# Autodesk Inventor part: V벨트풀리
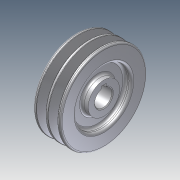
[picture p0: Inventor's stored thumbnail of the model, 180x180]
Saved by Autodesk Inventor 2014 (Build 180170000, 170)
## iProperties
Company: 한국ATC센터
Created: 2015-02
Part Number: V벨트풀리
Document SubType Name: Modeling
Designer: KYOUNG IL JANG
Density: 1 g/cm^3
Material: 일반
Appearance: 기본값
Author: KYOUNG IL JANG
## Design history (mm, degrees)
sketch "스케치1"
  geometry: L1 (0, 0)-(35, 0); L2 (35, 0)-(35, 55); L3 (35, 55)-(31.062, 55); L4 (31.062, 55)-(27.001, 42.5); L5 (27.001, 42.5)-(22.999, 42.5); L6 (22.999, 42.5)-(18.938, 55); L7 (18.938, 55)-(16.062, 55); L8 (16.062, 55)-(12.001, 42.5); L9 (12.001, 42.5)-(7.999, 42.5); L10 (7.999, 42.5)-(3.938, 55); L11 (3.938, 55)-(0, 55); L12 (0, 55)-(0, 0); L13 (5.4, 50.5)-(14.6, 50.5); L14 (20.4, 50.5)-(29.6, 50.5); 3 further points
  constraints: 28 end point, 8 parallel, 6 collinear, 4 point on line, 3 midpoint, 2 perpendicular, 1 horizontal, 1 vertical alignment
  dimensions: "d0" = 36 deg angle of L8 L10; "d1" = 9.2 distance of L14.start L14.end; "d2" = 4.5 distance between parallel lines of L13 L11; "d3" = 8 distance between parallel lines of L9 L13; "d4" = 10 distance from line of point (25, 42.5) L2; "d5" = 15 distance of point (25, 42.5) point (10, 42.5); "d6" = 35 distance of L1.start L1.end; "d7" = 101 diameter of L14 L1
revolve "회전1" sketch "스케치1" stored, may be unused: angle "d8" = 90 deg
fillet "모깎기1" dims "d9" = 2
fillet "모깎기2" dims "d10" = 0.5
fillet "모깎기3" dims "d11" = 1
sketch "스케치2"
  geometry: L1 (0, 0)-(8, 0); L2 (8, 0)-(8, 20); L3 (8, 20)-(17, 20); L4 (17, 20)-(17, 35); L5 (17, 35)-(0, 35); L6 (0, 35)-(0, 0); L7 (35, 35)-(27, 35); L8 (27, 35)-(27, 20); L9 (27, 20)-(35, 20); L10 (35, 20)-(35, 35); L11 (35, 53)-(35, -53) reference
  constraints: 20 end point, 6 parallel, 3 collinear, 3 perpendicular, 1 horizontal
  dimensions: "d12" = 40 diameter of L9 L1; "d13" = 70 diameter of L7 L1; "d14" = 8 distance between parallel lines of L10 L8; "d15" = 10 distance between parallel lines of L8 L4; "d16" = 9 distance between parallel lines of L4 L2
revolve "회전2" sketch "스케치2" stored, may be unused: angle "d17" = 90 deg
hole "구멍1" diameter "d20" = 22; stored, may be unused: countersink angle "d24" = 90 deg, drill point angle "d26" = 118 deg; dims "d18" = 10, "d19" = 10, "d21" = 6, "d22" = 4, "d23" = 2, "d25" = 8
sketch "스케치3"
  geometry: L1 (-14.8, -3)-(-7.8, -3); L2 (-7.8, -3)-(-7.8, 3); L3 (-7.8, 3)-(-14.8, 3); L4 (-14.8, 3)-(-14.8, -3); C1 r 11 at (0, 0) reference; 2 further points
  constraints: 8 end point, 2 parallel, 1 horizontal, 1 horizontal alignment, 1 midpoint, 1 perpendicular
  dimensions: "d27" = 25.8 dimension on C1 L4; "d28" = 6 distance of L3.end L1.start; "d29" = 7 distance between parallel lines of L4 L2
extrude "돌출1" cut sketch "스케치3" stored distance "d30" = 10; taper "d31" = 0 deg
fillet "모깎기4" dims "d32" = 3
chamfer "모따기1" distance "d33" = 1; stored, may be unused: second distance "d34" = 2, angle "d35" = 45 deg
node "솔리드1"
